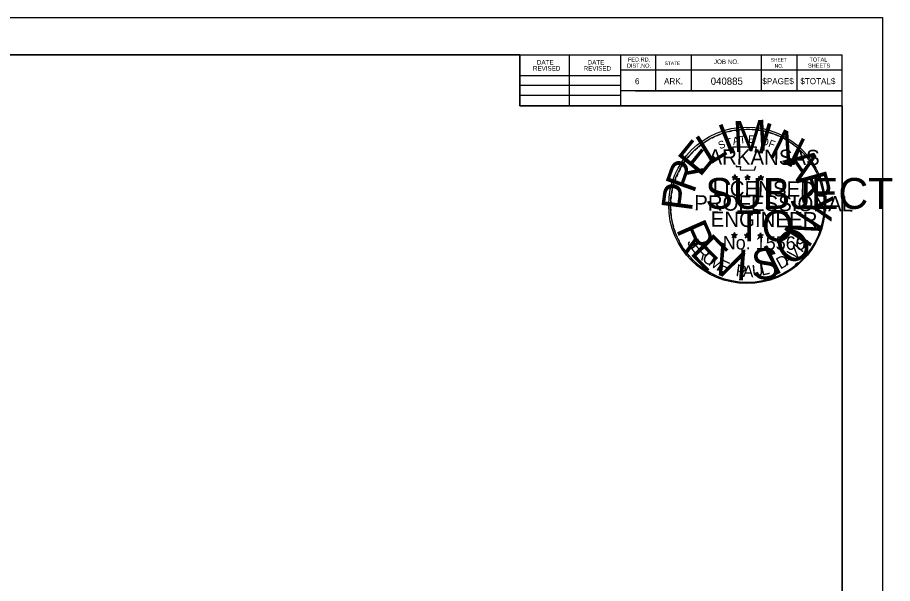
# Model space of a CAD drawing. Extents: x 60284.6 to 60318.8, y 53664 to 53686.
# Drawn here: x 60301.79 to 60318.8, y 53674.97 to 53685.97 of the extents above; entities that cross this region are included whole.
import ezdxf

# ---------------------------------------------------------------- set-up
doc = ezdxf.new("R2010")
doc.units = 0
for name, color, linetype in [('Level 1', 7, 'Continuous'), ('Level 37', 7, 'Continuous'), ('Level 62', 7, 'Continuous'), ('Level 63', 7, 'Continuous'), ('R_Border', 7, 'Continuous'), ('R_Border Notes', 7, 'Continuous'), ('R_No Plot', 7, 'Continuous'), ('Stamp Mask', 7, 'Continuous')]:
    doc.layers.add(name, color=color, linetype=linetype)

msp = doc.modelspace()

# ---------------------------------------------------------------- linework, layer by layer
at = {"layer": 'Level 1'}
msp.add_lwpolyline([(60317.819, 53674.964), (60317.819, 53684.249), (60311.555, 53684.249), (60311.555, 53685.237), (60286.201, 53685.237), (60286.201, 53664.691), (60303.668, 53664.691), (60317.819, 53664.691)], close=True, dxfattribs=at)
at = {"layer": 'Level 37'}
msp.add_lwpolyline([(60284.604, 53685.965), (60318.604, 53685.965), (60318.604, 53663.965), (60284.604, 53663.965)], close=True, dxfattribs=at)
at = {"layer": 'Level 62'}
msp.add_circle((60315.976, 53682.306), 1.492, dxfattribs=at)
at = {"layer": 'R_Border'}
for p, q in [((60315.68, 53682.87), (60315.733, 53682.854)), ((60315.68, 53682.87), (60315.718, 53682.869)), ((60315.68, 53682.87), (60315.718, 53682.867)), ((60315.68, 53682.87), (60315.714, 53682.861)), ((60315.68, 53682.87), (60315.714, 53682.856)), ((60315.68, 53682.87), (60315.714, 53682.854)), ((60315.68, 53682.87), (60315.714, 53682.848)), ((60315.702, 53682.81), (60315.733, 53682.854)), ((60315.702, 53682.81), (60315.714, 53682.852)), ((60315.702, 53682.81), (60315.718, 53682.847)), ((60315.702, 53682.81), (60315.72, 53682.845)), ((60315.702, 53682.81), (60315.725, 53682.841)), ((60315.702, 53682.81), (60315.733, 53682.841)), ((60315.702, 53682.81), (60315.733, 53682.837)), ((60315.733, 53682.911), (60315.725, 53682.87)), ((60315.733, 53682.911), (60315.725, 53682.874)), ((60315.733, 53682.911), (60315.729, 53682.874)), ((60315.733, 53682.854), (60315.733, 53682.911)), ((60315.733, 53682.911), (60315.742, 53682.87)), ((60315.733, 53682.911), (60315.74, 53682.874)), ((60315.733, 53682.911), (60315.735, 53682.874)), ((60315.784, 53682.87), (60315.733, 53682.854)), ((60315.764, 53682.808), (60315.733, 53682.854)), ((60315.764, 53682.808), (60315.733, 53682.841)), ((60315.764, 53682.808), (60315.733, 53682.837)), ((60315.784, 53682.87), (60315.736, 53682.867)), ((60315.764, 53682.808), (60315.736, 53682.841)), ((60315.784, 53682.87), (60315.742, 53682.863)), ((60315.784, 53682.87), (60315.742, 53682.859)), ((60315.764, 53682.808), (60315.742, 53682.852)), ((60315.764, 53682.808), (60315.742, 53682.847)), ((60315.764, 53682.808), (60315.747, 53682.854)), ((60315.784, 53682.87), (60315.749, 53682.859)), ((60315.784, 53682.87), (60315.755, 53682.856)), ((60315.784, 53682.87), (60315.757, 53682.854)), ((60315.927, 53682.869), (60315.98, 53682.854)), ((60315.927, 53682.869), (60315.965, 53682.867)), ((60315.927, 53682.869), (60315.965, 53682.863)), ((60315.927, 53682.869), (60315.965, 53682.861)), ((60315.927, 53682.869), (60315.964, 53682.854)), ((60315.927, 53682.869), (60315.964, 53682.852)), ((60315.927, 53682.869), (60315.964, 53682.847)), ((60315.949, 53682.808), (60315.98, 53682.854)), ((60315.949, 53682.808), (60315.965, 53682.848)), ((60315.949, 53682.808), (60315.965, 53682.847)), ((60315.949, 53682.808), (60315.967, 53682.845)), ((60315.949, 53682.808), (60315.973, 53682.839)), ((60315.949, 53682.808), (60315.98, 53682.839)), ((60315.949, 53682.808), (60315.98, 53682.837)), ((60315.98, 53682.907), (60315.973, 53682.869)), ((60315.98, 53682.907), (60315.973, 53682.87)), ((60315.98, 53682.907), (60315.975, 53682.87)), ((60315.98, 53682.854), (60315.98, 53682.907)), ((60315.98, 53682.907), (60315.989, 53682.869)), ((60315.98, 53682.907), (60315.987, 53682.87)), ((60315.98, 53682.907), (60315.982, 53682.87)), ((60316.031, 53682.869), (60315.98, 53682.854)), ((60316.011, 53682.808), (60315.98, 53682.854)), ((60316.011, 53682.808), (60315.98, 53682.839)), ((60316.011, 53682.808), (60315.98, 53682.837)), ((60316.031, 53682.869), (60315.986, 53682.867)), ((60316.011, 53682.808), (60315.986, 53682.839)), ((60316.031, 53682.869), (60315.989, 53682.861)), ((60316.031, 53682.869), (60315.989, 53682.859)), ((60316.011, 53682.808), (60315.989, 53682.852)), ((60316.011, 53682.808), (60315.989, 53682.845)), ((60316.011, 53682.808), (60315.995, 53682.852)), ((60316.031, 53682.869), (60315.997, 53682.856)), ((60316.031, 53682.869), (60316.002, 53682.854)), ((60316.031, 53682.869), (60316.004, 53682.852)), ((60316.189, 53682.867), (60316.242, 53682.848)), ((60316.189, 53682.867), (60316.231, 53682.861)), ((60316.189, 53682.867), (60316.227, 53682.859)), ((60316.189, 53682.867), (60316.227, 53682.856)), ((60316.189, 53682.867), (60316.226, 53682.852)), ((60316.189, 53682.867), (60316.226, 53682.847)), ((60316.189, 53682.867), (60316.226, 53682.847)), ((60316.209, 53682.806), (60316.242, 53682.848)), ((60316.209, 53682.806), (60316.227, 53682.847)), ((60316.209, 53682.806), (60316.231, 53682.841)), ((60316.209, 53682.806), (60316.231, 53682.839)), ((60316.209, 53682.806), (60316.242, 53682.839)), ((60316.209, 53682.806), (60316.238, 53682.837)), ((60316.209, 53682.806), (60316.246, 53682.832)), ((60316.242, 53682.903), (60316.233, 53682.869)), ((60316.242, 53682.903), (60316.238, 53682.867)), ((60316.242, 53682.903), (60316.238, 53682.867)), ((60316.242, 53682.848), (60316.242, 53682.903)), ((60316.242, 53682.903), (60316.253, 53682.867)), ((60316.242, 53682.903), (60316.249, 53682.867)), ((60316.242, 53682.903), (60316.246, 53682.867)), ((60316.293, 53682.867), (60316.242, 53682.848)), ((60316.271, 53682.806), (60316.242, 53682.848)), ((60316.271, 53682.806), (60316.242, 53682.839)), ((60316.271, 53682.806), (60316.242, 53682.832)), ((60316.293, 53682.867), (60316.248, 53682.861)), ((60316.271, 53682.806), (60316.248, 53682.837)), ((60316.293, 53682.867), (60316.253, 53682.859)), ((60316.293, 53682.867), (60316.253, 53682.854)), ((60316.271, 53682.806), (60316.253, 53682.847)), ((60316.271, 53682.806), (60316.253, 53682.841)), ((60316.271, 53682.806), (60316.257, 53682.847)), ((60316.293, 53682.867), (60316.26, 53682.852)), ((60316.293, 53682.867), (60316.262, 53682.852)), ((60316.293, 53682.867), (60316.268, 53682.848)), ((60315.672, 53681.745), (60315.725, 53681.729)), ((60315.672, 53681.745), (60315.711, 53681.744)), ((60315.672, 53681.745), (60315.709, 53681.738)), ((60315.672, 53681.745), (60315.709, 53681.738)), ((60315.672, 53681.745), (60315.709, 53681.731)), ((60315.672, 53681.745), (60315.709, 53681.729)), ((60315.672, 53681.745), (60315.709, 53681.727)), ((60315.691, 53681.689), (60315.725, 53681.729)), ((60315.691, 53681.689), (60315.709, 53681.729)), ((60315.691, 53681.689), (60315.711, 53681.722)), ((60315.691, 53681.689), (60315.713, 53681.722)), ((60315.691, 53681.689), (60315.725, 53681.72)), ((60315.691, 53681.689), (60315.718, 53681.716)), ((60315.691, 53681.689), (60315.725, 53681.714)), ((60315.725, 53681.786), (60315.714, 53681.749)), ((60315.725, 53681.786), (60315.718, 53681.745)), ((60315.725, 53681.786), (60315.72, 53681.745)), ((60315.755, 53681.685), (60315.722, 53681.714)), ((60315.725, 53681.729), (60315.725, 53681.786)), ((60315.725, 53681.786), (60315.733, 53681.745)), ((60315.725, 53681.786), (60315.733, 53681.745)), ((60315.725, 53681.786), (60315.725, 53681.745)), ((60315.777, 53681.745), (60315.725, 53681.729)), ((60315.755, 53681.685), (60315.725, 53681.729)), ((60315.755, 53681.685), (60315.725, 53681.716)), ((60315.755, 53681.685), (60315.727, 53681.716)), ((60315.777, 53681.745), (60315.729, 53681.744)), ((60315.777, 53681.745), (60315.733, 53681.738)), ((60315.777, 53681.745), (60315.733, 53681.736)), ((60315.755, 53681.685), (60315.733, 53681.729)), ((60315.755, 53681.685), (60315.733, 53681.722)), ((60315.777, 53681.745), (60315.74, 53681.734)), ((60315.755, 53681.685), (60315.74, 53681.729)), ((60315.777, 53681.745), (60315.744, 53681.731)), ((60315.777, 53681.745), (60315.747, 53681.729)), ((60315.92, 53681.745), (60315.973, 53681.729)), ((60315.92, 53681.745), (60315.958, 53681.742)), ((60315.92, 53681.745), (60315.958, 53681.738)), ((60315.92, 53681.745), (60315.958, 53681.736)), ((60315.92, 53681.745), (60315.956, 53681.731)), ((60315.92, 53681.745), (60315.956, 53681.727)), ((60315.92, 53681.745), (60315.956, 53681.723)), ((60315.938, 53681.685), (60315.973, 53681.729)), ((60315.938, 53681.685), (60315.958, 53681.727)), ((60315.938, 53681.685), (60315.958, 53681.72)), ((60315.938, 53681.685), (60315.96, 53681.72)), ((60315.938, 53681.685), (60315.965, 53681.716)), ((60315.938, 53681.685), (60315.973, 53681.716)), ((60315.938, 53681.685), (60315.973, 53681.712)), ((60315.973, 53681.782), (60315.964, 53681.745)), ((60315.973, 53681.782), (60315.965, 53681.745)), ((60315.973, 53681.782), (60315.967, 53681.745)), ((60316.002, 53681.685), (60315.971, 53681.712)), ((60315.973, 53681.729), (60315.973, 53681.782)), ((60315.973, 53681.782), (60315.98, 53681.744)), ((60315.973, 53681.782), (60315.98, 53681.744)), ((60315.973, 53681.782), (60315.973, 53681.745)), ((60316.022, 53681.744), (60315.973, 53681.729)), ((60316.002, 53681.685), (60315.973, 53681.729)), ((60316.002, 53681.685), (60315.973, 53681.716)), ((60316.002, 53681.685), (60315.975, 53681.716)), ((60316.022, 53681.744), (60315.978, 53681.744)), ((60316.022, 53681.744), (60315.98, 53681.736)), ((60316.022, 53681.744), (60315.98, 53681.736)), ((60316.002, 53681.685), (60315.98, 53681.727)), ((60316.002, 53681.685), (60315.98, 53681.722)), ((60316.022, 53681.744), (60315.987, 53681.731)), ((60316.002, 53681.685), (60315.987, 53681.727)), ((60316.022, 53681.744), (60315.993, 53681.729)), ((60316.022, 53681.744), (60315.995, 53681.727)), ((60316.182, 53681.742), (60316.235, 53681.723)), ((60316.182, 53681.742), (60316.22, 53681.738)), ((60316.182, 53681.742), (60316.22, 53681.734)), ((60316.182, 53681.742), (60316.218, 53681.731)), ((60316.182, 53681.742), (60316.218, 53681.727)), ((60316.182, 53681.742), (60316.216, 53681.723)), ((60316.182, 53681.742), (60316.216, 53681.72)), ((60316.202, 53681.681), (60316.235, 53681.723)), ((60316.202, 53681.681), (60316.218, 53681.723)), ((60316.202, 53681.681), (60316.22, 53681.716)), ((60316.202, 53681.681), (60316.224, 53681.716)), ((60316.202, 53681.681), (60316.227, 53681.712)), ((60316.202, 53681.681), (60316.233, 53681.712)), ((60316.202, 53681.681), (60316.235, 53681.709)), ((60316.235, 53681.78), (60316.226, 53681.742)), ((60316.235, 53681.78), (60316.227, 53681.742)), ((60316.235, 53681.78), (60316.231, 53681.742)), ((60316.264, 53681.681), (60316.233, 53681.712)), ((60316.264, 53681.681), (60316.233, 53681.709)), ((60316.235, 53681.723), (60316.235, 53681.78)), ((60316.235, 53681.78), (60316.242, 53681.742)), ((60316.235, 53681.78), (60316.242, 53681.742)), ((60316.235, 53681.78), (60316.235, 53681.742)), ((60316.286, 53681.742), (60316.235, 53681.723)), ((60316.264, 53681.681), (60316.235, 53681.723)), ((60316.264, 53681.681), (60316.238, 53681.712)), ((60316.286, 53681.742), (60316.24, 53681.738)), ((60316.286, 53681.742), (60316.242, 53681.734)), ((60316.286, 53681.742), (60316.242, 53681.731)), ((60316.264, 53681.681), (60316.242, 53681.716)), ((60316.264, 53681.681), (60316.246, 53681.723)), ((60316.264, 53681.681), (60316.248, 53681.723)), ((60316.286, 53681.742), (60316.253, 53681.729)), ((60316.286, 53681.742), (60316.255, 53681.723)), ((60316.286, 53681.742), (60316.257, 53681.723))]:
    msp.add_line(p, q, dxfattribs=at)
for points in [[(60315.691, 53683.447), (60315.727, 53683.323)], [(60316.211, 53683.306), (60316.233, 53683.35), (60316.129, 53683.345), (60316.152, 53683.444), (60315.691, 53683.447)], [(60315.762, 53683.087), (60315.762, 53683.072), (60315.845, 53683.07), (60315.837, 53683.002), (60316.114, 53683), (60316.143, 53683.077)], [(60315.733, 53682.911), (60315.764, 53682.808), (60315.68, 53682.87), (60315.784, 53682.87), (60315.702, 53682.81), (60315.733, 53682.911)], [(60315.98, 53682.907), (60316.011, 53682.808), (60315.927, 53682.869), (60316.031, 53682.869), (60315.949, 53682.808), (60315.98, 53682.907)], [(60316.242, 53682.903), (60316.271, 53682.806), (60316.189, 53682.867), (60316.293, 53682.867), (60316.209, 53682.806), (60316.242, 53682.903)], [(60315.725, 53681.786), (60315.755, 53681.685), (60315.672, 53681.745), (60315.777, 53681.745), (60315.691, 53681.689), (60315.725, 53681.786)], [(60315.973, 53681.782), (60316.002, 53681.685), (60315.92, 53681.745), (60316.022, 53681.744), (60315.938, 53681.685), (60315.973, 53681.782)], [(60316.235, 53681.78), (60316.264, 53681.681), (60316.182, 53681.742), (60316.286, 53681.742), (60316.202, 53681.681), (60316.235, 53681.78)], [(60316.922, 53681.146), (60316.914, 53681.17), (60316.958, 53681.207)], [(60316.955, 53681.212), (60316.962, 53681.19), (60316.918, 53681.152)], [(60316.962, 53681.194), (60316.918, 53681.156)], [(60316.962, 53681.19), (60316.92, 53681.154)]]:
    msp.add_lwpolyline(points, dxfattribs=at)
for centre, radius in [((60315.734, 53682.853), 0.0256), ((60315.734, 53682.853), 0.0231), ((60315.734, 53682.853), 0.0215), ((60315.734, 53682.853), 0.0197), ((60315.734, 53682.853), 0.0172), ((60315.734, 53682.853), 0.016), ((60315.734, 53682.853), 0.0147), ((60315.734, 53682.853), 0.0127), ((60315.734, 53682.853), 0.0111), ((60315.734, 53682.853), 0.00922), ((60315.734, 53682.853), 0.00735), ((60315.734, 53682.853), 0.00548), ((60315.734, 53682.853), 0.0044), ((60315.734, 53682.853), 0.00214), ((60315.981, 53682.851), 0.0256), ((60315.981, 53682.851), 0.0231), ((60315.981, 53682.851), 0.0215), ((60315.981, 53682.851), 0.0197), ((60315.981, 53682.851), 0.0172), ((60315.981, 53682.851), 0.016), ((60315.981, 53682.851), 0.0147), ((60315.981, 53682.851), 0.0127), ((60315.981, 53682.851), 0.0111), ((60315.981, 53682.851), 0.00922), ((60315.981, 53682.851), 0.00735), ((60315.981, 53682.851), 0.00548), ((60315.981, 53682.851), 0.0044), ((60315.981, 53682.851), 0.00214), ((60316.244, 53682.848), 0.0256), ((60316.244, 53682.848), 0.0231), ((60316.244, 53682.848), 0.0215), ((60316.244, 53682.848), 0.0197), ((60316.244, 53682.848), 0.0172), ((60316.244, 53682.848), 0.016), ((60316.244, 53682.848), 0.0147), ((60316.244, 53682.848), 0.0127), ((60316.244, 53682.848), 0.0111), ((60316.244, 53682.848), 0.00922), ((60316.244, 53682.848), 0.00735), ((60316.244, 53682.848), 0.00548), ((60316.244, 53682.848), 0.0044), ((60316.244, 53682.848), 0.00214), ((60315.725, 53681.729), 0.0256), ((60315.725, 53681.729), 0.0231), ((60315.725, 53681.729), 0.0215), ((60315.725, 53681.729), 0.0197), ((60315.725, 53681.729), 0.0172), ((60315.725, 53681.729), 0.016), ((60315.725, 53681.729), 0.0147), ((60315.725, 53681.729), 0.0127), ((60315.725, 53681.729), 0.0111), ((60315.725, 53681.729), 0.00922), ((60315.725, 53681.729), 0.00735), ((60315.725, 53681.729), 0.00548), ((60315.725, 53681.729), 0.0044), ((60315.725, 53681.729), 0.00214), ((60315.973, 53681.727), 0.0256), ((60315.973, 53681.727), 0.0231), ((60315.973, 53681.727), 0.0215), ((60315.973, 53681.727), 0.0197), ((60315.973, 53681.727), 0.0172), ((60315.973, 53681.727), 0.016), ((60315.973, 53681.727), 0.0147), ((60315.973, 53681.727), 0.0127), ((60315.973, 53681.727), 0.0111), ((60315.973, 53681.727), 0.00922), ((60315.973, 53681.727), 0.00735), ((60315.973, 53681.727), 0.00548), ((60315.973, 53681.727), 0.0044), ((60315.973, 53681.727), 0.00214), ((60316.235, 53681.724), 0.0256), ((60316.235, 53681.724), 0.0231), ((60316.235, 53681.724), 0.0215), ((60316.235, 53681.724), 0.0197), ((60316.235, 53681.724), 0.0172), ((60316.235, 53681.724), 0.016), ((60316.235, 53681.724), 0.0147), ((60316.235, 53681.724), 0.0127), ((60316.235, 53681.724), 0.0111), ((60316.235, 53681.724), 0.00922), ((60316.235, 53681.724), 0.00735), ((60316.235, 53681.724), 0.00548), ((60316.235, 53681.724), 0.0044), ((60316.235, 53681.724), 0.00214)]:
    msp.add_circle(centre, radius, dxfattribs=at)
at = {"layer": 'R_Border Notes'}
for p, q in [((60286.201, 53685.237), (60317.819, 53685.237)), ((60311.555, 53684.249), (60311.555, 53685.237)), ((60312.523, 53684.249), (60312.523, 53685.217)), ((60313.509, 53685.237), (60313.509, 53684.249)), ((60314.193, 53685.237), (60314.193, 53684.543)), ((60314.887, 53685.237), (60314.887, 53684.543)), ((60316.245, 53685.237), (60316.245, 53684.543)), ((60316.939, 53685.237), (60316.939, 53684.543)), ((60317.819, 53664.691), (60317.819, 53685.237)), ((60317.819, 53684.943), (60313.509, 53684.943)), ((60317.819, 53684.945), (60317.819, 53684.945)), ((60311.555, 53684.835), (60313.509, 53684.835)), ((60311.555, 53684.649), (60313.509, 53684.649)), ((60317.819, 53684.543), (60313.509, 53684.543)), ((60313.805, 53684.543), (60317.819, 53684.543)), ((60311.555, 53684.455), (60313.509, 53684.455)), ((60317.819, 53684.249), (60311.555, 53684.249))]:
    msp.add_line(p, q, dxfattribs=at)
at = {"layer": 'R_No Plot'}
msp.add_lwpolyline([(60286.201, 53664.691), (60286.201, 53685.237), (60311.555, 53685.237), (60311.555, 53684.249), (60313.201, 53684.249), (60313.509, 53684.249), (60313.509, 53684.249), (60313.509, 53684.249), (60317.819, 53684.249), (60317.819, 53683.957), (60317.819, 53680.626), (60317.819, 53664.691)], close=True, dxfattribs=at)
at = {"layer": 'Stamp Mask'}
msp.add_circle((60315.969, 53682.315), 1.521, dxfattribs=at)

# ---------------------------------------------------------------- texts
at = {"layer": 'Level 62'}
for s, rotation, p in [('I', 22.0105, (60315.58, 53683.284)), ('M', 2.6943, (60315.712, 53683.35)), ('I', 343.3781, (60316.132, 53683.362)), ('L', 31.6686, (60315.232, 53683.087)), ('N', 333.7199, (60316.369, 53683.285)), ('E', 50.9849, (60315.055, 53682.846)), ('A', 304.7456, (60316.651, 53683.182)), ('R', 70.3011, (60314.935, 53682.529)), ('R', 285.4294, (60316.912, 53682.877)), ('P', 82.6089, (60314.896, 53682.18)), ('Y', 266.1131, (60317.047, 53682.553)), ('N', 57.1378, (60317.161, 53681.461)), ('R', 293.7639, (60314.584, 53681.851)), ('O', 36.5754, (60316.798, 53681.106)), ('E', 314.3262, (60314.842, 53681.383)), ('V', 334.8885, (60315.214, 53681.058)), ('I', 355.4508, (60315.742, 53680.866)), ('S', 5.732, (60316.09, 53680.855)), ('I', 26.2943, (60316.492, 53680.938))]:
    msp.add_text(s, height=0.6, rotation=rotation, dxfattribs=at).set_placement(p)
for s, p in [('SUBJECT', (60315.16, 53682.246)), ('TO', (60315.766, 53681.616))]:
    msp.add_text(s, height=0.6, dxfattribs=at).set_placement(p)
at = {"layer": 'Level 63'}
msp.add_text('JOB NO.', height=0.0879, dxfattribs=at).set_placement((60315.327, 53685.061))
at = {"layer": 'R_Border'}
for s, height, rotation, p in [('-', 0.237, 28.3942, (60315.315, 53683.532)), ('-', 0.237, 23.9096, (60315.409, 53683.578)), ('-', 0.237, 18.7785, (60315.504, 53683.618)), ('-', 0.237, 13.2326, (60315.616, 53683.653)), ('-', 0.237, 9.8217, (60315.714, 53683.676)), ('T', 0.148, 5.6252, (60315.83, 53683.512)), ('-', 0.237, 5.4992, (60315.824, 53683.691)), ('-', 0.237, 359.7886, (60315.938, 53683.702)), ('E', 0.148, 0.4347, (60315.993, 53683.526)), ('-', 0.237, 357.3454, (60316.048, 53683.698)), ('-', 0.237, 351.7641, (60316.156, 53683.689)), ('-', 0.237, 346.8073, (60316.264, 53683.673)), ('-', 0.237, 341.9386, (60316.358, 53683.647)), ('-', 0.237, 337.4575, (60316.466, 53683.614)), ('-', 0.237, 333.7235, (60316.561, 53683.576)), ('-', 0.237, 38.5531, (60315.07, 53683.363)), ('-', 0.237, 35.8341, (60315.139, 53683.42)), ('-', 0.237, 33.666, (60315.225, 53683.479)), ('S', 0.148, 21.1964, (60315.443, 53683.402)), ('T', 0.148, 16.006, (60315.579, 53683.451)), ('A', 0.148, 10.8156, (60315.703, 53683.488)), ('O', 0.148, 350.0539, (60316.231, 53683.495)), ('F', 0.148, 339.6731, (60316.372, 53683.458)), ('-', 0.237, 329.2433, (60316.645, 53683.532)), ('-', 0.237, 325.4651, (60316.74, 53683.475)), ('-', 0.237, 48.0254, (60314.936, 53683.233)), ('-', 0.237, 42.5646, (60315.004, 53683.303)), ('ARKANSAS', 0.2969, 359.6024, (60315.22, 53683.11)), ('-', 0.237, 320.1321, (60316.83, 53683.413)), ('-', 0.237, 315.181, (60316.92, 53683.339)), ('-', 0.237, 53.8349, (60314.813, 53683.077)), ('-', 0.237, 50.2166, (60314.875, 53683.162)), ('-', 0.237, 309.4821, (60317.002, 53683.257)), ('-', 0.237, 306.2546, (60317.078, 53683.167)), ('-', 0.237, 62.4738, (60314.72, 53682.907)), ('-', 0.237, 57.673, (60314.765, 53682.997)), ('-', 0.208, 303.2777, (60317.151, 53683.081)), ('-', 0.237, 299.2708, (60317.197, 53682.991)), ('-', 0.237, 71.9969, (60314.646, 53682.724)), ('-', 0.237, 67.3767, (60314.681, 53682.817)), ('-', 0.237, 294.2652, (60317.244, 53682.9)), ('-', 0.237, 290.1752, (60317.285, 53682.817)), ('-', 0.237, 75.0634, (60314.617, 53682.618)), ('LICENSED', 0.2969, 359.6024, (60315.303, 53682.495)), ('-', 0.237, 284.7257, (60317.316, 53682.729)), ('-', 0.237, 84.7887, (60314.584, 53682.41)), ('-', 0.237, 80.8037, (60314.595, 53682.513)), ('PROFESSIONAL', 0.29686, 359.6024, (60314.943, 53682.216)), ('-', 0.237, 280.1517, (60317.345, 53682.618)), ('-', 0.237, 276.1986, (60317.371, 53682.504)), ('-', 0.237, 88.6646, (60314.58, 53682.306)), ('-', 0.237, 273.9325, (60317.378, 53682.396)), ('-', 0.237, 93.7983, (60314.584, 53682.198)), ('-', 0.237, 98.5503, (60314.595, 53682.097)), ('ENGINEER', 0.2969, 359.6024, (60315.264, 53681.899)), ('-', 0.237, 263.1196, (60317.378, 53682.205)), ('-', 0.237, 269.5431, (60317.382, 53682.304)), ('-', 0.237, 101.3173, (60314.612, 53681.989)), ('-', 0.237, 105.0602, (60314.637, 53681.901)), ('-', 0.237, 255.365, (60317.349, 53682.007)), ('-', 0.237, 260.5977, (60317.365, 53682.108)), ('-', 0.237, 108.6898, (60314.668, 53681.81)), ('-', 0.237, 252.4705, (60317.323, 53681.899)), ('-', 0.237, 113.6667, (60314.705, 53681.718)), ('-', 0.237, 115.3313, (60314.751, 53681.626)), ('J', 0.229, 303.9209, (60314.796, 53681.591)), ('No. 15560', 0.2612, 359.6024, (60315.498, 53681.46)), ('S', 0.229, 53.5227, (60317.09, 53681.446)), ('-', 0.237, 244.2221, (60317.248, 53681.707)), ('-', 0.237, 247.4911, (60317.29, 53681.799)), ('-', 0.237, 120.0495, (60314.802, 53681.538)), ('-', 0.237, 125.4958, (60314.863, 53681.456)), ('E', 0.229, 308.618, (60314.86, 53681.496)), ('R', 0.229, 314.7784, (60314.956, 53681.379)), ('V', 0.229, 41.4844, (60316.882, 53681.237)), ('I', 0.229, 49.9999, (60317.034, 53681.38)), ('-', 0.237, 238.6736, (60317.189, 53681.597)), ('-', 0.237, 130.3205, (60314.929, 53681.374)), ('-', 0.237, 133.8262, (60315.005, 53681.293)), ('O', 0.229, 321.6761, (60315.078, 53681.261)), ('M', 0.229, 328.1357, (60315.204, 53681.164)), ('D', 0.229, 28.5809, (60316.616, 53681.066)), ('A', 0.229, 34.8903, (60316.751, 53681.142)), ('-', 0.237, 233.4476, (60317.063, 53681.419)), ('-', 0.237, 233.4476, (60317.133, 53681.5)), ('-', 0.237, 138.5362, (60315.081, 53681.223)), ('-', 0.237, 144.2487, (60315.167, 53681.163)), ('E', 0.229, 336.4966, (60315.381, 53681.062)), ('P', 0.229, 351.9783, (60315.741, 53680.944)), ('A', 0.229, 357.9896, (60315.888, 53680.925)), ('U', 0.229, 5.7635, (60316.078, 53680.924)), ('L', 0.229, 13.0992, (60316.257, 53680.946)), ('-', 0.237, 215.3387, (60316.832, 53681.188)), ('-', 0.237, 225.3677, (60316.993, 53681.333)), ('-', 0.237, 147.6922, (60315.247, 53681.106)), ('-', 0.237, 151.1728, (60315.332, 53681.058)), ('-', 0.237, 154.2026, (60315.412, 53681.02)), ('-', 0.237, 203.854, (60316.577, 53681.035)), ('-', 0.237, 206.9592, (60316.671, 53681.08)), ('-', 0.237, 211.8515, (60316.753, 53681.132)), ('-', 0.237, 158.1636, (60315.504, 53680.98)), ('-', 0.237, 162.4007, (60315.606, 53680.948)), ('-', 0.237, 167.1579, (60315.711, 53680.925)), ('-', 0.237, 172.7179, (60315.824, 53680.908)), ('-', 0.237, 176.1207, (60315.936, 53680.897)), ('-', 0.237, 181.1942, (60316.046, 53680.901)), ('-', 0.237, 185.4191, (60316.167, 53680.91)), ('-', 0.237, 190.8882, (60316.277, 53680.928)), ('-', 0.237, 195.0767, (60316.385, 53680.958)), ('-', 0.237, 200.3208, (60316.486, 53680.994))]:
    msp.add_text(s, height=height, rotation=rotation, dxfattribs=at).set_placement(p)
at = {"layer": 'R_Border Notes'}
for s, height, p in [('DATE', 0.0879, (60311.888, 53685.051)), ('DATE', 0.0879, (60312.874, 53685.051)), ('DIST.NO.', 0.0782, (60313.637, 53684.991)), ('FED.RD.', 0.0782, (60313.657, 53685.109)), ('STATE', 0.0684, (60314.369, 53685.041)), ('JOB NO.', 0.0879, (60315.327, 53685.061)), ('SHEET', 0.0684, (60316.431, 53685.109)), ('NO.', 0.0684, (60316.509, 53684.991)), ('SHEETS', 0.0782, (60317.155, 53684.991)), ('TOTAL', 0.0782, (60317.183, 53685.109)), ('REVISED', 0.0879, (60311.81, 53684.933)), ('REVISED', 0.0879, (60312.796, 53684.933)), ('6', 0.117, (60313.793, 53684.669)), ('ARK.', 0.1172, (60314.359, 53684.669)), ('040885', 0.14, (60315.265, 53684.658)), ('$PAGE$', 0.1172, (60316.269, 53684.669)), ('$TOTAL$', 0.1172, (60317.008, 53684.669))]:
    msp.add_text(s, height=height, dxfattribs=at).set_placement(p)

doc.saveas('drawing.dxf')
